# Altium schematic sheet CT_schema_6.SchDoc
size 218 x 258 mm
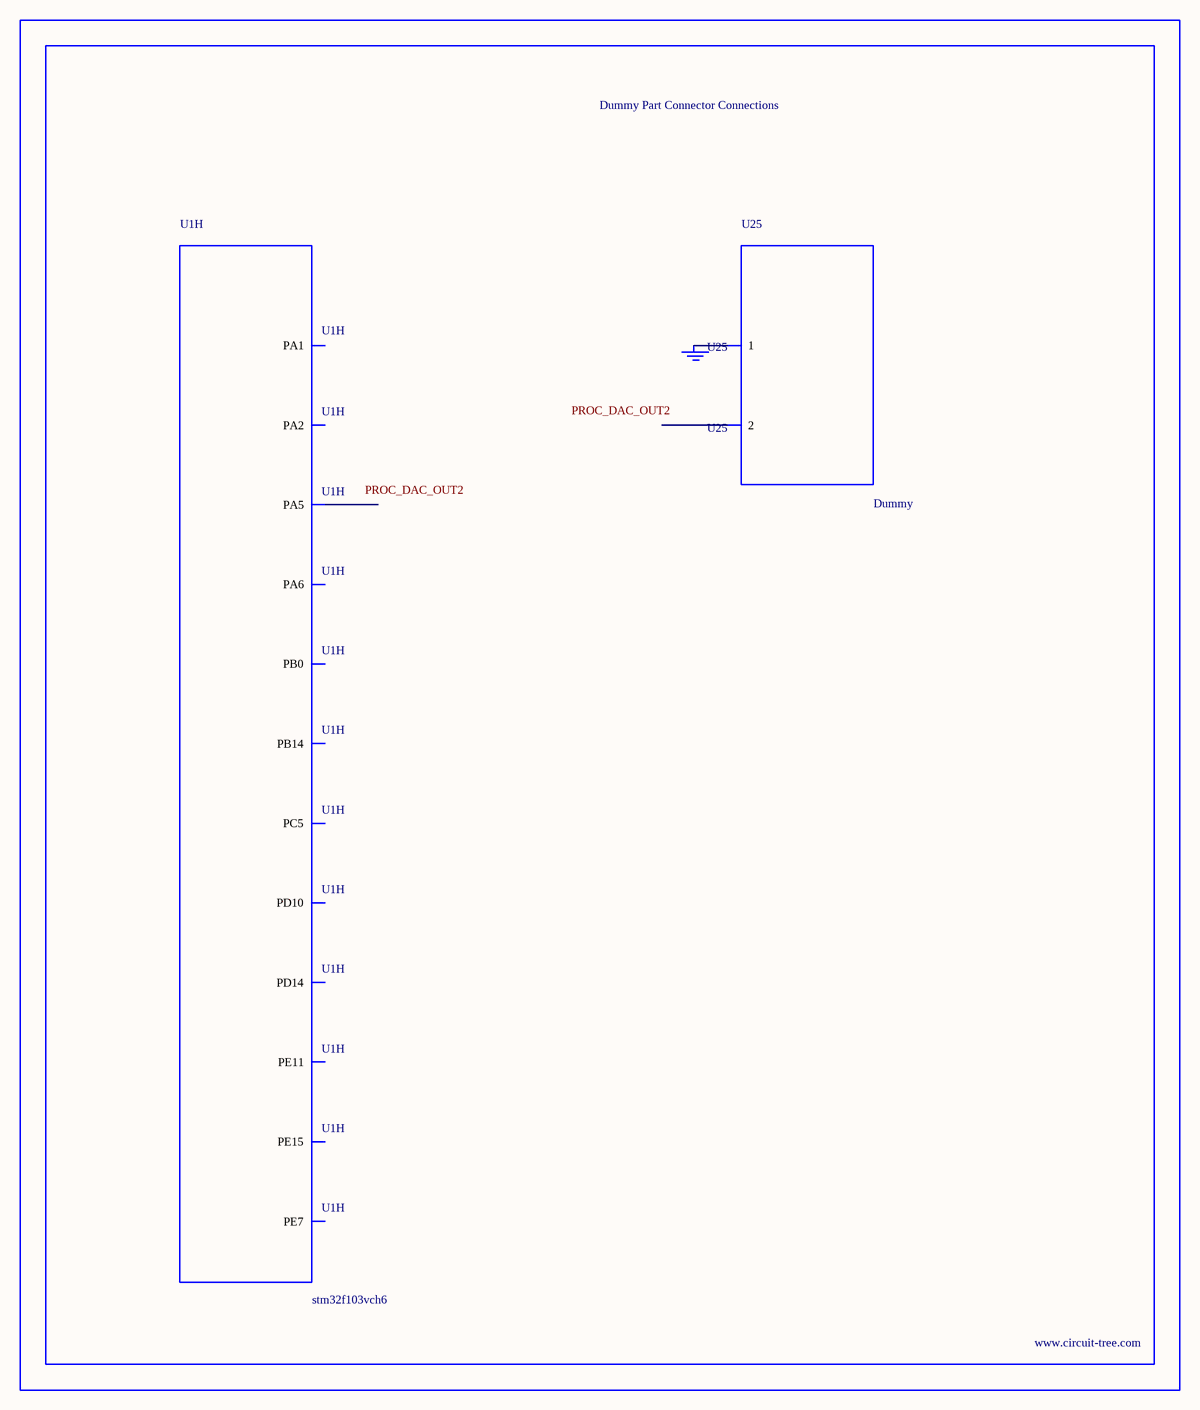
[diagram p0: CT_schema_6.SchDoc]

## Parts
BORDER5  (no value)
GND_INSTANCE_5_0  (no value)
U1  stm32f103vch6  [LFBGA100]  (part H of 8)
U25  Dummy  [DUMMY_PACKAGE_235]

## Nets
NetGND_INSTANCE_5_0_0: GND_INSTANCE_5_0.0(GND) U25.1

Not connected (* = marked no-connect by the designer): U1 H2(PA1) H3(PA5) H4(PC5) H5(PE7) H6(PE11) H7(PE15) H8(PB14) H9(PD10) H10(PD14) J2(PA2) J3(PA6) J4(PB0); U25 2

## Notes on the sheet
- Labels drawn without touching a wire or pin: PROC_DAC_OUT2

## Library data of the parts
BORDER5 = BORDER_PAGE5
GND_INSTANCE_5_0 = GND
